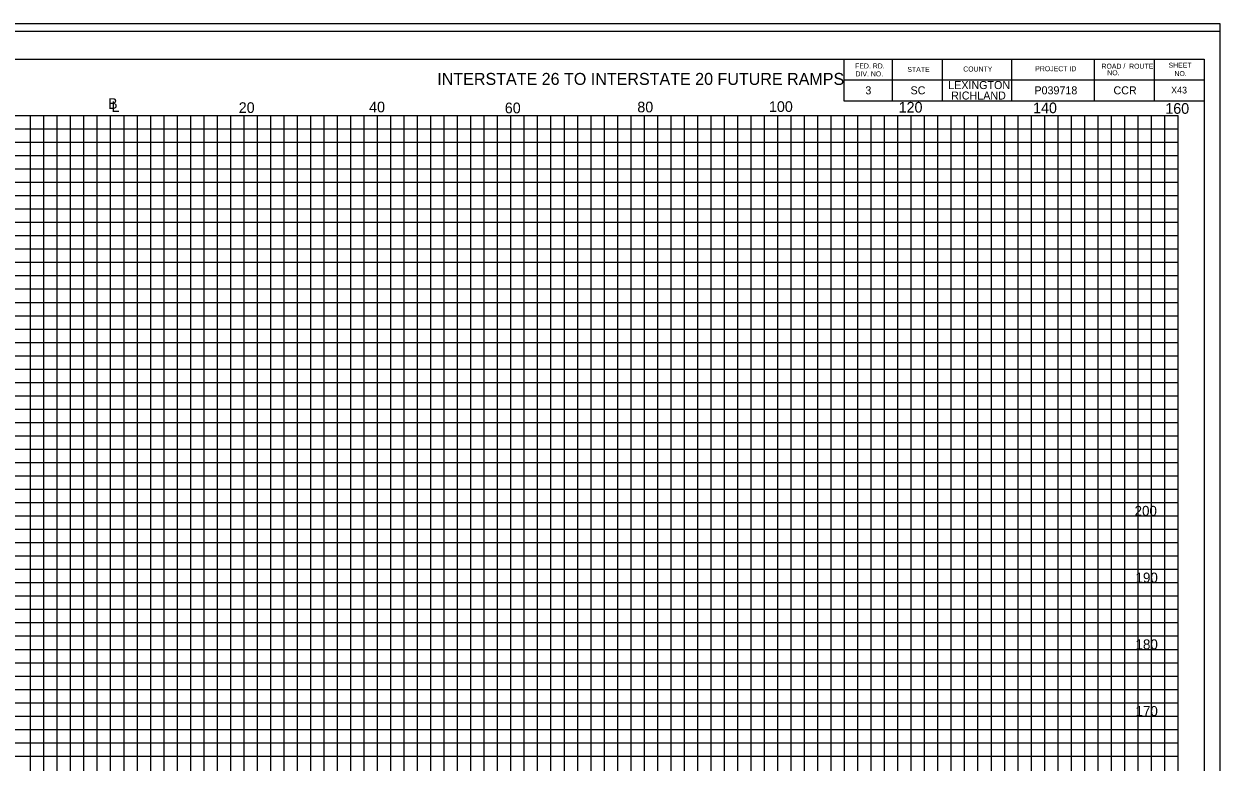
# Model space of a CAD drawing. Extents: x 967 to 1326, y 964 to 1184.
# Drawn here: x 1147 to 1326.3, y 1073.1 to 1183.7 of the extents above; entities that cross this region are included whole.
import ezdxf

# ---------------------------------------------------------------- set-up
doc = ezdxf.new("R2010")
doc.units = 0
for name, color, linetype in [('Default', 7, 'Continuous'), ('RD_SHT_Bndy', 7, 'Continuous'), ('RD_SHT_IplotShp', 7, 'Continuous'), ('RD_SHT_MjGrid', 7, 'Continuous'), ('RD_SHT_MnGrid', 7, 'Continuous'), ('RD_SHT_TX', 7, 'Continuous'), ('RD_Sketch1', 7, 'Continuous')]:
    doc.layers.add(name, color=color, linetype=linetype)

msp = doc.modelspace()

# ---------------------------------------------------------------- linework, layer by layer
at = {"layer": 'RD_SHT_Bndy'}
for p, q in [((996.11, 1178.46), (1323.89, 1178.46)), ((1269.89, 1178.46), (1269.89, 1172.21)), ((1277.14, 1178.46), (1277.14, 1172.21)), ((1284.64, 1178.46), (1284.64, 1172.21)), ((1295, 1178.46), (1295, 1172.21)), ((1307.43, 1178.46), (1307.43, 1172.21)), ((1316.39, 1178.46), (1316.39, 1172.21)), ((1323.89, 1178.46), (1323.89, 968.98)), ((1269.89, 1175.33), (1323.89, 1175.33)), ((1269.89, 1172.21), (1323.89, 1172.21))]:
    msp.add_line(p, q, dxfattribs=at)
at = {"layer": 'RD_SHT_IplotShp'}
for points in [[(967.41, 963.72), (1326.28, 963.72), (1326.28, 1183.72), (967.41, 1183.72)], [(988.52, 964.84), (1326.28, 964.84), (1326.28, 1182.6), (988.52, 1182.6)]]:
    msp.add_lwpolyline(points, close=True, dxfattribs=at)
at = {"layer": 'RD_SHT_MjGrid'}
for p, q in [((1000, 1170), (1320, 1170)), ((1150, 1000), (1150, 1170)), ((1160, 1000), (1160, 1170)), ((1170, 1000), (1170, 1170)), ((1180, 1000), (1180, 1170)), ((1190, 1000), (1190, 1170)), ((1200, 1000), (1200, 1170)), ((1210, 1000), (1210, 1170)), ((1220, 1000), (1220, 1170)), ((1230, 1000), (1230, 1170)), ((1240, 1000), (1240, 1170)), ((1250, 1000), (1250, 1170)), ((1260, 1000), (1260, 1170)), ((1270, 1000), (1270, 1170)), ((1280, 1000), (1280, 1170)), ((1290, 1000), (1290, 1170)), ((1300, 1000), (1300, 1170)), ((1310, 1000), (1310, 1170)), ((1320, 1000), (1320, 1170)), ((1000, 1160), (1320, 1160)), ((1000, 1150), (1320, 1150)), ((1000, 1140), (1320, 1140)), ((1000, 1130), (1320, 1130)), ((1000, 1120), (1320, 1120)), ((1000, 1110), (1320, 1110)), ((1000, 1100), (1320, 1100)), ((1000, 1090), (1320, 1090)), ((1000, 1080), (1320, 1080))]:
    msp.add_line(p, q, dxfattribs=at)
at = {"layer": 'RD_SHT_MnGrid'}
for p, q in [((1148, 1000), (1148, 1170)), ((1152, 1000), (1152, 1170)), ((1154, 1000), (1154, 1170)), ((1156, 1000), (1156, 1170)), ((1158, 1000), (1158, 1170)), ((1162, 1000), (1162, 1170)), ((1164, 1000), (1164, 1170)), ((1166, 1000), (1166, 1170)), ((1168, 1000), (1168, 1170)), ((1172, 1000), (1172, 1170)), ((1174, 1000), (1174, 1170)), ((1176, 1000), (1176, 1170)), ((1178, 1000), (1178, 1170)), ((1182, 1000), (1182, 1170)), ((1184, 1000), (1184, 1170)), ((1186, 1000), (1186, 1170)), ((1188, 1000), (1188, 1170)), ((1192, 1000), (1192, 1170)), ((1194, 1000), (1194, 1170)), ((1196, 1000), (1196, 1170)), ((1198, 1000), (1198, 1170)), ((1202, 1000), (1202, 1170)), ((1204, 1000), (1204, 1170)), ((1206, 1000), (1206, 1170)), ((1208, 1000), (1208, 1170)), ((1212, 1000), (1212, 1170)), ((1214, 1000), (1214, 1170)), ((1216, 1000), (1216, 1170)), ((1218, 1000), (1218, 1170)), ((1222, 1000), (1222, 1170)), ((1224, 1000), (1224, 1170)), ((1226, 1000), (1226, 1170)), ((1228, 1000), (1228, 1170)), ((1232, 1000), (1232, 1170)), ((1234, 1000), (1234, 1170)), ((1236, 1000), (1236, 1170)), ((1238, 1000), (1238, 1170)), ((1242, 1000), (1242, 1170)), ((1244, 1000), (1244, 1170)), ((1246, 1000), (1246, 1170)), ((1248, 1000), (1248, 1170)), ((1252, 1000), (1252, 1170)), ((1254, 1000), (1254, 1170)), ((1256, 1000), (1256, 1170)), ((1258, 1000), (1258, 1170)), ((1262, 1000), (1262, 1170)), ((1264, 1000), (1264, 1170)), ((1266, 1000), (1266, 1170)), ((1268, 1000), (1268, 1170)), ((1272, 1000), (1272, 1170)), ((1274, 1000), (1274, 1170)), ((1276, 1000), (1276, 1170)), ((1278, 1000), (1278, 1170)), ((1282, 1000), (1282, 1170)), ((1284, 1000), (1284, 1170)), ((1286, 1000), (1286, 1170)), ((1288, 1000), (1288, 1170)), ((1292, 1000), (1292, 1170)), ((1294, 1000), (1294, 1170)), ((1296, 1000), (1296, 1170)), ((1298, 1000), (1298, 1170)), ((1302, 1000), (1302, 1170)), ((1304, 1000), (1304, 1170)), ((1306, 1000), (1306, 1170)), ((1308, 1000), (1308, 1170)), ((1312, 1000), (1312, 1170)), ((1314, 1000), (1314, 1170)), ((1316, 1000), (1316, 1170)), ((1318, 1000), (1318, 1170)), ((1000, 1168), (1320, 1168)), ((1000, 1166), (1320, 1166)), ((1000, 1164), (1320, 1164)), ((1000, 1162), (1320, 1162)), ((1000, 1158), (1320, 1158)), ((1000, 1156), (1320, 1156)), ((1000, 1154), (1320, 1154)), ((1000, 1152), (1320, 1152)), ((1000, 1148), (1320, 1148)), ((1000, 1146), (1320, 1146)), ((1000, 1144), (1320, 1144)), ((1000, 1142), (1320, 1142)), ((1000, 1138), (1320, 1138)), ((1000, 1136), (1320, 1136)), ((1000, 1134), (1320, 1134)), ((1000, 1132), (1320, 1132)), ((1000, 1128), (1320, 1128)), ((1000, 1126), (1320, 1126)), ((1000, 1124), (1320, 1124)), ((1000, 1122), (1320, 1122)), ((1000, 1118), (1320, 1118)), ((1000, 1116), (1320, 1116)), ((1000, 1114), (1320, 1114)), ((1000, 1112), (1320, 1112)), ((1000, 1108), (1320, 1108)), ((1000, 1106), (1320, 1106)), ((1000, 1104), (1320, 1104)), ((1000, 1102), (1320, 1102)), ((1000, 1098), (1320, 1098)), ((1000, 1096), (1320, 1096)), ((1000, 1094), (1320, 1094)), ((1000, 1092), (1320, 1092)), ((1000, 1088), (1320, 1088)), ((1000, 1086), (1320, 1086)), ((1000, 1084), (1320, 1084)), ((1000, 1082), (1320, 1082)), ((1000, 1078), (1320, 1078)), ((1000, 1076), (1320, 1076)), ((1000, 1074), (1320, 1074))]:
    msp.add_line(p, q, dxfattribs=at)
at = {"layer": 'RD_Sketch1'}
msp.add_lwpolyline([(967.41, 963.72), (1326.28, 963.72), (1326.28, 1183.72), (967.41, 1183.72)], close=True, dxfattribs=at)

# ---------------------------------------------------------------- texts
at = {"layer": 'Default'}
for s, height, p in [('X43', 1, (1318.95, 1173.3)), ('200', 1.5, (1313.47, 1110)), ('190', 1.5, (1313.61, 1100)), ('180', 1.5, (1313.61, 1090)), ('170', 1.5, (1313.61, 1080))]:
    msp.add_text(s, height=height, dxfattribs=at).set_placement(p)
at = {"layer": 'RD_SHT_TX'}
for s, height, p in [('SHEET', 0.75, (1318.56, 1177.16)), ('FED. RD.', 0.75, (1271.58, 1177.05)), ('DIV. NO.', 0.75, (1271.64, 1175.86)), ('STATE', 0.75, (1279.41, 1176.53)), ('COUNTY', 0.75, (1287.78, 1176.59)), ('PROJECT ID', 0.75, (1298.58, 1176.63)), ('ROAD /  ROUTE', 0.75, (1308.51, 1177.01)), ('   NO.', 0.75, (1308.51, 1176.03)), ('NO.', 0.75, (1319.45, 1175.91)), ('3', 1.2, (1273.12, 1173.17)), ('SC', 1.2, (1279.89, 1173.17)), ('LEXINGTON', 1.2, (1285.54, 1173.96)), ('P039718', 1.2, (1298.46, 1173.17)), ('CCR', 1.2, (1310.31, 1173.17)), ('B', 1.6, (1159.61, 1170.99)), ('RICHLAND', 1.2, (1285.97, 1172.39)), ('L', 1.6, (1160.12, 1170.54)), ('20', 1.6, (1179.2, 1170.38)), ('40', 1.6, (1198.74, 1170.47)), ('60', 1.6, (1219.08, 1170.33)), ('80', 1.6, (1238.94, 1170.47)), ('100', 1.6, (1258.67, 1170.53)), ('120', 1.6, (1278.11, 1170.43)), ('140', 1.6, (1298.26, 1170.34)), ('160', 1.6, (1318.08, 1170.25))]:
    msp.add_text(s, height=height, dxfattribs=at).set_placement(p)
msp.add_text('INTERSTATE 26 TO INTERSTATE 20 FUTURE RAMPS', height=1.8, rotation=0, dxfattribs=at).set_placement((1208.96, 1174.58))

doc.saveas('drawing.dxf')
